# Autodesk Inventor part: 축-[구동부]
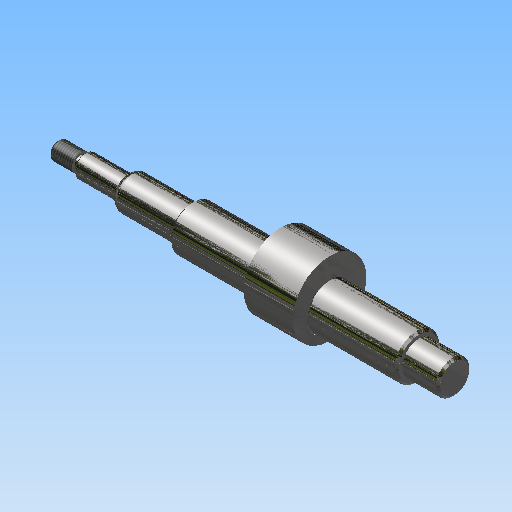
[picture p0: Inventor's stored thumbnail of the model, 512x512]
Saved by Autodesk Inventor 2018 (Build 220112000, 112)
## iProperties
Created: 2015-12
Part Number: 축-[구동부]
Document SubType Name: Modeling
Designer: mdu
Density: 7.86 g/cm^3
Material: 강철, 연강
Mass: 421.834 g
Surface Area: 119.066 cm^2
Volume: 53.6685 cm^3
Appearance: 반광택
Author: mdu
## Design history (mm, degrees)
sketch "스케치1"
  geometry: L1 (62, 100.9)-(62, 67.1) reference; L2 (51, 101.2)-(51, 84) reference; L3 (-51, 84)-(-51, 101.2) reference; L4 (-62, 67.1)-(-62, 100.9) reference; L5 (-51.6, 91.5)-(-61.4, 91.5) reference; L6 (51.6, 91.5)-(61.4, 91.5) reference; L7 (67, 84)-(-111, 84); L8 (-77, 64.201)-(-77, 103.799) reference; L9 (67, 84)-(67, 91.5); L10 (67, 91.5)-(51, 91.5); L11 (51, 91.5)-(51, 94); L12 (51, 94)-(-51, 94); L13 (-51, 94)-(-51, 91.5); L14 (-51, 91.5)-(-79, 91.5); L15 (-79, 91.5)-(-79, 89); L16 (-79, 89)-(-99, 89); L17 (-99, 89)-(-99, 87); L18 (-100.5, 88)-(-111, 88); L19 (-111, 88)-(-111, 84); L20 (-99, 87)-(-100.5, 87); L21 (-100.5, 87)-(-100.5, 88); 2 further points
  constraints: 32 end point, 7 parallel, 6 point on line, 5 perpendicular, 2 collinear, 2 horizontal, 1 midpoint, 4 other
  dimensions: "d0" = 5 distance from line of L7.start L1; "d2" = 2 distance between parallel lines of L15 L8; "d3" = 20 diameter of L12 L7; "d4" = 10 diameter of L16 L7; "d5" = 1.5 distance of L17.end L20.end; "d6" = 6 diameter of L20 L7; "d7" = 20 distance of L15.end L16.end; "d8" = 12 distance between parallel lines of L17 L19; "d9" = 8 diameter of L18 L7
revolve "회전1" sketch "스케치1" stored, may be unused: angle "d10" = 90 deg
sketch "스케치2"
  geometry: C1 r 10 at (84, 0) reference; C2 r 10 at (84, 0) reference; C3 r 16.5 at (87, 0); 1 further point
  constraints: 1 centre point, 1 horizontal alignment
  dimensions: "d11" = 33 diameter of C3; "d12" = 3 distance of C3.centre C1.centre
extrude "돌출1" join sketch "스케치2" stored distance "d13" = 22; taper "d14" = 0 deg
chamfer "모따기1" distance "d15" = 1; stored, may be unused: second distance "d16" = 2, angle "d17" = 45 deg
feature "스레드1" dims "d18" = 10, "d19" = 0
node "작업 평면1"
sketch "스케치3"
  geometry: L1 (-5.5, -1.5)-(3.5, -1.5); L2 (3.5, 1.5)-(-5.5, 1.5); L3 (-10, -4)-(-10, 4) reference; A1 r 1.5 centre (3.5, 0) between (3.5, -1.5) and (3.5, 1.5); A2 r 1.5 centre (-5.5, 0) between (-5.5, 1.5) and (-5.5, -1.5); 2 further points
  constraints: 4 end point, 4 point on circle, 4 tangent, 2 centre point, 1 horizontal, 1 horizontal alignment, 1 midpoint, 1 parallel
  dimensions: "d20" = 3 distance between parallel lines of L1 L2; "d21" = 12 dimension on A1 A2; "d22" = 3 distance edge to line of A2 L3
extrude "돌출2" cut sketch "스케치3" distance "d23" = 1.8; taper "d24" = 0 deg
fillet "모깎기1" dims "d25" = 0.3
fillet "모깎기2" dims "d26" = 3
node "솔리드1"
node "참조1"
node "참조2"
node "참조3"
node "참조4"
node "참조5"
node "투영된 루프1"
